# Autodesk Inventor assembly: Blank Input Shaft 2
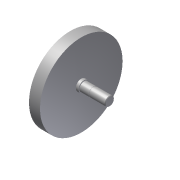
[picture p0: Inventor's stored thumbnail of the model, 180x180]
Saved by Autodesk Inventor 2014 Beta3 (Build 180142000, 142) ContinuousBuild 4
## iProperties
Created: 2011-01
Part Number: Blank Input Shaft 2
Document SubType Name: Assembly
Designer: Beta-8540w
ClientObjectVersion: 1
Author: Beta-8540w
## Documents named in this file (2)
- C:\Inventor 2014 Essentials\Assemblies\Chapter 09\Design Accelerators\Blank Input Shaft 2.iam
- C:\Inventor 2014 Essentials\Assemblies\Chapter 09\Design Accelerators\Blank Input Shaft 2.ipt
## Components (1 placed, 1 different names)
1. Blank Input Shaft 2:1
